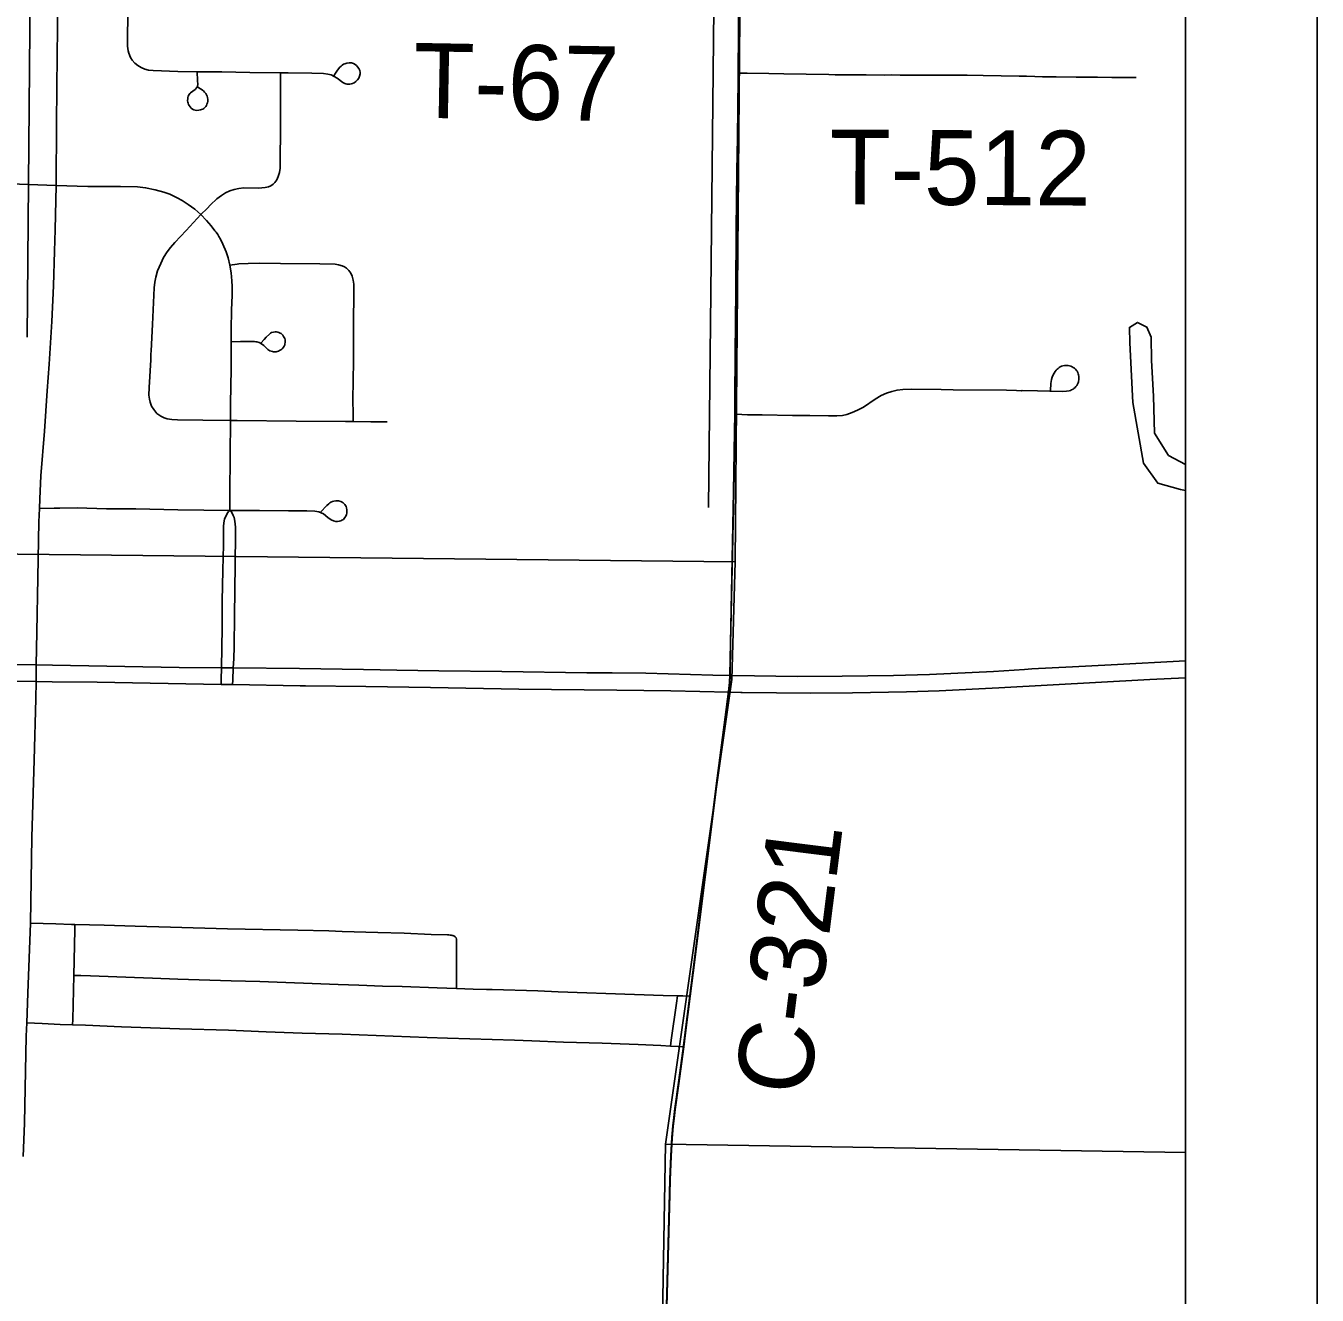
# Model space of a CAD drawing. Extents: x 0 to 34, y 0 to 22.
# Drawn here: x 8.019 to 9, y 17.308 to 18.272 of the extents above; entities that cross this region are included whole.
import ezdxf

# ---------------------------------------------------------------- set-up
doc = ezdxf.new("R2010")
doc.units = 0
for name, color, linetype in [('GM_X_Corporation', 7, 'Continuous'), ('GM_X_County_Road', 7, 'Continuous'), ('GM_X_County_Road_Text', 7, 'Continuous'), ('GM_X_Minor_Lake', 7, 'Continuous'), ('GM_X_Minor_River', 7, 'Continuous'), ('GM_X_State_Route', 7, 'Continuous'), ('GM_X_Township_Road', 7, 'Continuous'), ('GM_X_Township_Road_Text', 7, 'Continuous'), ('SH_Data', 7, 'Continuous')]:
    doc.layers.add(name, color=color, linetype=linetype)

msp = doc.modelspace()

# ---------------------------------------------------------------- linework, layer by layer
at = {"layer": 'GM_X_Corporation'}
for points in [[(2.1, 14.1), (8.9, 14.1), (8.9, 20.9), (5.89055, 20.9)], [(8.9, 14.37894), (8.9, 20.9)], [(8.56052, 18.29711), (8.56015, 18.23686), (8.56012, 18.23234), (8.55954, 18.18707), (8.55908, 18.16202), (8.55853, 18.11743), (8.55826, 18.07146), (8.55781, 18.02296), (8.55745, 17.98877), (8.55741, 17.97779), (8.55735, 17.96394), (8.55646, 17.91855), (8.55413, 17.8032), (8.55384, 17.77938), (8.55343, 17.77344), (8.55279, 17.76663), (8.55006, 17.74716), (8.54421, 17.70088), (8.52569, 17.55343), (8.52344, 17.53573), (8.51965, 17.50581), (8.51853, 17.49739), (8.51481, 17.46953), (8.51202, 17.44979), (8.5112, 17.44296), (8.51046, 17.43679), (8.50973, 17.42799), (8.50887, 17.41389), (8.50817, 17.39625), (8.50787, 17.38524), (8.50714, 17.35667), (8.50556, 17.3001)], [(8.50556, 17.3001), (8.50714, 17.35667), (8.50787, 17.38524), (8.50817, 17.39625), (8.50887, 17.41389), (8.50973, 17.42799), (8.51046, 17.43679), (8.5112, 17.44296), (8.51202, 17.44979), (8.51481, 17.46953), (8.51853, 17.49739), (8.51965, 17.50581), (8.52344, 17.53573), (8.52569, 17.55343), (8.54421, 17.70088), (8.55006, 17.74716), (8.55279, 17.76663), (8.55343, 17.77344), (8.55384, 17.77938), (8.55413, 17.8032), (8.55646, 17.91855), (8.55735, 17.96394), (8.55741, 17.97779), (8.55745, 17.98877), (8.55781, 18.02296), (8.55826, 18.07146), (8.55853, 18.11743), (8.55908, 18.16202), (8.55954, 18.18707), (8.56012, 18.23234), (8.56015, 18.23686), (8.56052, 18.29711)]]:
    msp.add_lwpolyline(points, dxfattribs=at)
for points in [[(7.52848, 18.83427), (8.56457, 18.82324), (8.56257, 18.42645), (8.55788, 17.86518), (7.51498, 17.8763)], [(8.9, 17.41639), (8.9, 18.42344), (8.56257, 18.42645), (8.55788, 17.86518), (8.55531, 17.77577), (8.50493, 17.42275)], [(7.51498, 17.8763), (8.55788, 17.86518), (8.55531, 17.77577), (8.50493, 17.42275), (8.49555, 16.88277), (7.49907, 16.90775)], [(8.9, 16.4075), (8.9, 17.41639), (8.50493, 17.42275), (8.49555, 16.88277), (8.48586, 16.41255)]]:
    msp.add_lwpolyline(points, close=True, dxfattribs=at)
at = {"layer": 'GM_X_County_Road'}
msp.add_line((8.56037, 18.2363), (8.56075, 18.29655), dxfattribs=at)
for points in [[(8.0419, 18.15097), (8.04211, 18.19851), (8.04274, 18.25005), (8.04302, 18.28863), (8.04319, 18.30453)], [(8.55763, 17.97724), (8.55768, 17.98822), (8.55804, 18.02241), (8.55849, 18.0709), (8.55876, 18.11688), (8.55931, 18.16146), (8.55977, 18.18651), (8.56034, 18.23178), (8.56037, 18.2363)], [(8.02909, 17.90551), (8.02935, 17.91304), (8.03033, 17.93044), (8.03291, 17.96425), (8.03512, 17.99497), (8.03647, 18.0152), (8.03868, 18.04766), (8.03983, 18.07469), (8.04065, 18.1011), (8.04115, 18.11736), (8.0419, 18.15097)], [(8.55406, 17.77883), (8.55435, 17.80265), (8.55668, 17.918), (8.55758, 17.96339), (8.55763, 17.97724)], [(8.02662, 17.77409), (8.02676, 17.7849), (8.02679, 17.78677), (8.02712, 17.81165), (8.0279, 17.85327), (8.02874, 17.89539), (8.02909, 17.90551)], [(8.02226, 17.59065), (8.02329, 17.6559), (8.02511, 17.71438), (8.02646, 17.76103), (8.02662, 17.77409)], [(8.55302, 17.76608), (8.55365, 17.77288), (8.55406, 17.77883)], [(8.52367, 17.53518), (8.52591, 17.55287), (8.54444, 17.70032), (8.55029, 17.7466), (8.55302, 17.76608)], [(8.01949, 17.51487), (8.02025, 17.53756), (8.02226, 17.59065)], [(8.51876, 17.49683), (8.51988, 17.50525), (8.52367, 17.53518)], [(8.01675, 17.41339), (8.0177, 17.43885), (8.01916, 17.50487), (8.01949, 17.51487)], [(8.49865, 17.00885), (8.49937, 17.03847), (8.50075, 17.0913), (8.50197, 17.14476), (8.5044, 17.23552), (8.50579, 17.29955), (8.50737, 17.35612), (8.50809, 17.38469), (8.5084, 17.39569), (8.50909, 17.41334), (8.50996, 17.42743), (8.51069, 17.43624), (8.51143, 17.44241), (8.51225, 17.44924), (8.51504, 17.46898), (8.51876, 17.49683)]]:
    msp.add_lwpolyline(points, dxfattribs=at)
at = {"layer": 'GM_X_Minor_Lake'}
msp.add_lwpolyline([(8.9, 17.93891), (8.88708, 17.94598), (8.87634, 17.96282), (8.87557, 17.99092), (8.87403, 18.01789), (8.87388, 18.03573), (8.87058, 18.04337), (8.86344, 18.04688), (8.85735, 18.04316), (8.85758, 18.03138), (8.86002, 17.98618), (8.86812, 17.94014), (8.87887, 17.92482), (8.89619, 17.92005), (8.9, 17.91938)], dxfattribs=at)
at = {"layer": 'GM_X_Minor_River'}
for points in [[(8.55117, 19.1356), (8.54966, 19.01986), (8.54597, 18.88176), (8.54328, 18.70341), (8.54041, 18.48254), (8.54164, 18.28513), (8.53923, 18.06955), (8.53751, 17.90633)], [(8.03098, 18.72881), (8.02449, 18.51975), (8.022, 18.29848), (8.01975, 18.03583)]]:
    msp.add_lwpolyline(points, dxfattribs=at)
at = {"layer": 'GM_X_State_Route'}
msp.add_line((8.55302, 17.76608), (8.56202, 17.76588), dxfattribs=at)
for points in [[(8.55406, 17.77883), (8.57247, 17.77844), (8.60482, 17.77811), (8.63902, 17.77819), (8.6782, 17.77888), (8.70556, 17.77963), (8.72172, 17.78021), (8.75403, 17.7817), (8.77762, 17.78333), (8.78319, 17.78384), (8.81421, 17.7853), (8.8434, 17.78689), (8.9, 17.7898)], [(7.99618, 17.78735), (8.02679, 17.78677), (8.03907, 17.78653), (8.13543, 17.78485), (8.16741, 17.7846), (8.17646, 17.78451), (8.22683, 17.78404), (8.27532, 17.78327), (8.3008, 17.78277), (8.33251, 17.78222), (8.3804, 17.78185), (8.44505, 17.78084), (8.46433, 17.78079), (8.4898, 17.78044), (8.54076, 17.77911), (8.55406, 17.77883)], [(7.95935, 17.77485), (8.02662, 17.77409), (8.03893, 17.77394), (8.07313, 17.77358), (8.16712, 17.77203), (8.17012, 17.77198), (8.17595, 17.77188), (8.2273, 17.77094), (8.23128, 17.77091)], [(8.23128, 17.77091), (8.27705, 17.77052), (8.32617, 17.76968), (8.3933, 17.76838), (8.4679, 17.76756), (8.50894, 17.76706), (8.55302, 17.76608)], [(8.56202, 17.76588), (8.56302, 17.76585), (8.61524, 17.76541), (8.64693, 17.76567), (8.68795, 17.7663), (8.71279, 17.76714), (8.75812, 17.76927), (8.87297, 17.77567), (8.9, 17.77706)]]:
    msp.add_lwpolyline(points, dxfattribs=at)
at = {"layer": 'GM_X_Township_Road'}
for points in [[(8.09655, 18.30419), (8.09648, 18.29765), (8.0961, 18.26281), (8.09616, 18.25666), (8.0966, 18.25311), (8.09704, 18.25143), (8.09841, 18.24811), (8.09964, 18.24612), (8.10157, 18.2439), (8.10385, 18.24199), (8.10638, 18.24045), (8.10912, 18.23931), (8.11201, 18.23857), (8.1156, 18.23815), (8.13421, 18.23745), (8.14909, 18.23736)], [(8.21241, 18.23654), (8.21817, 18.23647), (8.23623, 18.23627), (8.24498, 18.23603), (8.24817, 18.23561), (8.2507, 18.23491), (8.25309, 18.23383), (8.25531, 18.23246), (8.25973, 18.22909), (8.26122, 18.22829), (8.26208, 18.22803), (8.2629, 18.22786), (8.26373, 18.22778), (8.26492, 18.22782), (8.26611, 18.22803), (8.26701, 18.22828), (8.26826, 18.22896), (8.26962, 18.22988), (8.27082, 18.23107), (8.27178, 18.23247), (8.27246, 18.23401), (8.27285, 18.23563), (8.27287, 18.23667), (8.2725, 18.23826), (8.27179, 18.2398), (8.27081, 18.24117), (8.2701, 18.24197), (8.26915, 18.24271), (8.26772, 18.24357), (8.26616, 18.24405), (8.26449, 18.24417), (8.26282, 18.24396), (8.2612, 18.24345), (8.2603, 18.24304), (8.25921, 18.24233), (8.25829, 18.24168), (8.25735, 18.2408), (8.2563, 18.23966), (8.25503, 18.23788), (8.25406, 18.2362), (8.25296, 18.23426)], [(8.14916, 18.22576), (8.15115, 18.22461), (8.15209, 18.22406), (8.15299, 18.22345), (8.15378, 18.22279), (8.15468, 18.22193), (8.15558, 18.22078), (8.15616, 18.21975), (8.15653, 18.21876), (8.15686, 18.2177), (8.15708, 18.21629), (8.15703, 18.2149), (8.15682, 18.21362), (8.15645, 18.21263), (8.15604, 18.21181), (8.15547, 18.21095), (8.15468, 18.20996), (8.15415, 18.20951), (8.15321, 18.20889), (8.15242, 18.20856), (8.15141, 18.20829), (8.1502, 18.20803), (8.14868, 18.20794), (8.14736, 18.20815), (8.14652, 18.20844), (8.14541, 18.20897), (8.14447, 18.20976), (8.14366, 18.21066), (8.14291, 18.21169), (8.14247, 18.21242), (8.14207, 18.21334), (8.14185, 18.21432), (8.14174, 18.21517), (8.14181, 18.21702), (8.14198, 18.21789), (8.14225, 18.21883), (8.1428, 18.21993), (8.14337, 18.22069), (8.14401, 18.22132), (8.14749, 18.22395), (8.14871, 18.22532), (8.14923, 18.22643), (8.14945, 18.22764), (8.14934, 18.23074), (8.14909, 18.23736)], [(8.14909, 18.23736), (8.15223, 18.23735), (8.16779, 18.23718), (8.18894, 18.23678), (8.21241, 18.23654)], [(8.15178, 18.1288), (8.15653, 18.13357), (8.15913, 18.1362), (8.16407, 18.14081), (8.16744, 18.14339), (8.17054, 18.14528), (8.17381, 18.1468), (8.17724, 18.14794), (8.18078, 18.14868), (8.18438, 18.14904), (8.19554, 18.14897), (8.20058, 18.14937), (8.20317, 18.14991), (8.20504, 18.15068), (8.20678, 18.15182), (8.20813, 18.1532), (8.20956, 18.15527), (8.21067, 18.15767), (8.21155, 18.1608), (8.21195, 18.164), (8.21202, 18.17026), (8.21226, 18.19322), (8.21239, 18.22982), (8.21241, 18.23654)], [(8.56037, 18.2363), (8.56682, 18.23621), (8.58345, 18.23599), (8.59476, 18.23584), (8.61174, 18.23548), (8.62894, 18.23512), (8.63388, 18.23506), (8.64087, 18.235), (8.65731, 18.23486), (8.67094, 18.23483), (8.67641, 18.23489), (8.6832, 18.23476), (8.69249, 18.23463), (8.69877, 18.23463), (8.70898, 18.23463), (8.71835, 18.23464), (8.73407, 18.23464), (8.7461, 18.23447), (8.77355, 18.23399), (8.77918, 18.23396), (8.78552, 18.23376), (8.79119, 18.23356), (8.80177, 18.23342), (8.8169, 18.23328), (8.83302, 18.23313), (8.844, 18.23303), (8.8577, 18.23294), (8.86248, 18.23291)], [(7.99503, 18.15257), (8.00701, 18.15228), (8.0419, 18.15097)], [(8.15178, 18.1288), (8.14712, 18.1329), (8.1422, 18.1366), (8.13757, 18.13961), (8.1338, 18.14168), (8.12823, 18.14426), (8.12363, 18.14595), (8.1171, 18.14774), (8.10986, 18.14917), (8.10377, 18.14985), (8.09081, 18.15022), (8.0659, 18.15008), (8.0419, 18.15097)], [(8.11839, 17.97785), (8.11612, 17.98069), (8.11442, 17.98341), (8.11324, 17.98629), (8.11266, 17.98871), (8.11236, 17.9918), (8.11244, 17.99741), (8.11372, 18.01854), (8.11368, 18.01978), (8.11389, 18.02165), (8.11387, 18.02289), (8.11408, 18.02538), (8.11503, 18.04528), (8.11628, 18.07327), (8.11674, 18.0776), (8.11748, 18.08126), (8.11894, 18.08602), (8.12127, 18.09179), (8.12345, 18.09627), (8.1261, 18.10049), (8.12875, 18.10394), (8.13213, 18.1076), (8.14055, 18.11678), (8.15178, 18.1288)], [(8.17386, 18.09047), (8.17254, 18.09599), (8.17099, 18.10063), (8.16859, 18.10629), (8.16665, 18.1102), (8.16553, 18.11231), (8.16464, 18.11378), (8.16346, 18.11549), (8.16252, 18.11647), (8.15957, 18.12017), (8.15603, 18.12445), (8.15178, 18.1288)], [(8.26747, 17.97156), (8.26741, 17.97762), (8.26731, 17.9882), (8.26773, 18.01746), (8.2678, 18.04921), (8.26796, 18.06663), (8.26799, 18.07597), (8.26764, 18.07906), (8.26681, 18.08206), (8.26576, 18.08432), (8.26432, 18.08634), (8.26251, 18.08805), (8.26098, 18.08911), (8.2593, 18.08992), (8.25631, 18.09079), (8.25396, 18.0911), (8.2422, 18.09146), (8.21238, 18.09161), (8.19621, 18.09181), (8.18764, 18.0916), (8.18067, 18.09133), (8.17943, 18.09118), (8.17386, 18.09047)], [(8.17482, 18.0323), (8.17496, 18.04145), (8.17518, 18.0563), (8.17548, 18.06752), (8.17551, 18.0742), (8.17539, 18.0785), (8.17519, 18.08155), (8.17487, 18.08456), (8.17386, 18.09047)], [(8.19347, 18.03228), (8.1944, 18.03215), (8.19618, 18.03161), (8.19787, 18.03069), (8.19953, 18.02939), (8.2028, 18.02638), (8.20351, 18.0259), (8.20429, 18.02544), (8.20528, 18.02503), (8.20616, 18.02481), (8.20705, 18.02467), (8.20803, 18.02463), (8.20902, 18.0247), (8.20988, 18.02487), (8.21071, 18.02508), (8.21164, 18.02551), (8.21252, 18.02602), (8.21323, 18.02651), (8.21414, 18.02736), (8.2147, 18.02812), (8.21512, 18.02894), (8.21552, 18.02993), (8.21573, 18.03072), (8.21585, 18.03166), (8.21593, 18.03258), (8.21575, 18.03381), (8.21551, 18.03467), (8.21511, 18.03557), (8.21469, 18.03635), (8.2141, 18.03714), (8.21358, 18.0377), (8.21272, 18.03842), (8.2121, 18.03882), (8.21108, 18.03931), (8.21033, 18.03956), (8.20926, 18.03974), (8.20828, 18.0398), (8.20708, 18.03964), (8.2056, 18.03916), (8.20474, 18.03873), (8.20384, 18.03807), (8.20145, 18.0358), (8.19979, 18.03389), (8.19746, 18.0312)], [(8.17431, 17.97255), (8.17445, 17.98535), (8.17474, 18.01139), (8.1748, 18.019), (8.17481, 18.02068), (8.1748, 18.02301), (8.1748, 18.02663), (8.17482, 18.0323)], [(8.17482, 18.0323), (8.18192, 18.03234), (8.19255, 18.0324), (8.19347, 18.03228)], [(8.55763, 17.97724), (8.56275, 17.97698), (8.56713, 17.97675), (8.57834, 17.97669), (8.60135, 17.97626), (8.61442, 17.97619), (8.62872, 17.97594), (8.63504, 17.97607), (8.63946, 17.97634), (8.64258, 17.97705), (8.64675, 17.97846), (8.6508, 17.98025), (8.65525, 17.98269), (8.66408, 17.98853), (8.66884, 17.99131), (8.67271, 17.9931), (8.67673, 17.99451), (8.68087, 17.99549), (8.68508, 17.99605), (8.69184, 17.99626), (8.71418, 17.99605), (8.72353, 17.99582), (8.76397, 17.99546), (8.77144, 17.99512), (8.77517, 17.99503), (8.77577, 17.9952), (8.78757, 17.99498), (8.80636, 17.99443), (8.80943, 17.99473), (8.81156, 17.995), (8.81263, 17.99534), (8.81346, 17.99574), (8.81452, 17.99633), (8.81519, 17.99684), (8.81604, 17.99756), (8.81668, 17.99824), (8.81735, 17.99909), (8.8179, 17.99992), (8.81839, 18.00094), (8.81868, 18.00184), (8.81901, 18.00388), (8.81891, 18.00593), (8.81867, 18.00706), (8.81846, 18.00794), (8.81805, 18.00896), (8.81756, 18.0098), (8.81706, 18.01052), (8.81626, 18.01143), (8.81554, 18.01208), (8.81464, 18.01271), (8.81389, 18.01315), (8.81279, 18.01363), (8.81184, 18.01393), (8.81081, 18.01416), (8.8099, 18.0143), (8.80874, 18.01428), (8.80793, 18.01418), (8.8067, 18.01393), (8.80583, 18.01364), (8.80479, 18.01315), (8.80403, 18.01269), (8.80311, 18.01199), (8.80246, 18.01142), (8.80167, 18.01057), (8.80094, 18.00969), (8.8001, 18.00846), (8.79938, 18.00718), (8.79856, 18.00526), (8.79807, 18.00352), (8.79769, 18.00043), (8.79734, 17.99518)], [(8.11839, 17.97785), (8.1214, 17.97578), (8.12404, 17.97446), (8.12628, 17.97375), (8.1298, 17.97313), (8.13409, 17.97288), (8.15333, 17.97259), (8.17431, 17.97255)], [(8.17378, 17.90418), (8.17385, 17.91628), (8.174, 17.94613), (8.17431, 17.97255)], [(8.17431, 17.97255), (8.17952, 17.97255), (8.22434, 17.97194), (8.26169, 17.97163), (8.26747, 17.97156)], [(8.26747, 17.97156), (8.28098, 17.97138), (8.29343, 17.97134)], [(8.21828, 17.90389), (8.23225, 17.90381), (8.23841, 17.90346), (8.24148, 17.90299), (8.24324, 17.90239), (8.24488, 17.90152), (8.2483, 17.89884), (8.25084, 17.89704), (8.25252, 17.89622), (8.25433, 17.8958), (8.25567, 17.89568), (8.25695, 17.89586), (8.25805, 17.89615), (8.25904, 17.89662), (8.26009, 17.89732), (8.26131, 17.89865), (8.26201, 17.89988), (8.26242, 17.90104), (8.26265, 17.90215), (8.26274, 17.90341), (8.26282, 17.90459), (8.26253, 17.9061), (8.26214, 17.90705), (8.26171, 17.90784), (8.26119, 17.90865), (8.26073, 17.90918), (8.25986, 17.90994), (8.25915, 17.9104), (8.25823, 17.91084), (8.25643, 17.91134), (8.25457, 17.91143), (8.25275, 17.91109), (8.25171, 17.9108), (8.25056, 17.91033), (8.24973, 17.90981), (8.24895, 17.90922), (8.2474, 17.90788), (8.24282, 17.90277)], [(8.02909, 17.90551), (8.04041, 17.90575), (8.04476, 17.90584), (8.0578, 17.90599), (8.08016, 17.90543), (8.10252, 17.90523), (8.1342, 17.90471), (8.17378, 17.90418)], [(8.16712, 17.77203), (8.1672, 17.77572), (8.16741, 17.7846), (8.16812, 17.81527), (8.16807, 17.83519), (8.1686, 17.85885), (8.16903, 17.8781), (8.16892, 17.89204), (8.1693, 17.89466), (8.16985, 17.89742), (8.17079, 17.89989), (8.17219, 17.90257), (8.17288, 17.90341), (8.17378, 17.90418)], [(8.17818, 17.89042), (8.17816, 17.89148), (8.17769, 17.89588), (8.177, 17.89868), (8.1764, 17.90038), (8.17545, 17.90246), (8.17481, 17.90326), (8.17378, 17.90418)], [(8.17378, 17.90418), (8.18141, 17.90407), (8.19633, 17.90402), (8.21828, 17.90389)], [(8.17646, 17.78451), (8.17674, 17.79152), (8.17711, 17.80073), (8.17734, 17.824), (8.17778, 17.86315), (8.17823, 17.88617), (8.17818, 17.89042)], [(8.17595, 17.77188), (8.17609, 17.77523), (8.17646, 17.78451)], [(8.02226, 17.59065), (8.0417, 17.59009), (8.05347, 17.58963), (8.05605, 17.58958)], [(8.05518, 17.55085), (8.05596, 17.58553), (8.05605, 17.58958)], [(8.05605, 17.58958), (8.07833, 17.5891), (8.10192, 17.58834), (8.12863, 17.58764), (8.17211, 17.58638), (8.22554, 17.58539), (8.24915, 17.58472), (8.25907, 17.58426), (8.28638, 17.58349), (8.30627, 17.58307), (8.32676, 17.58209), (8.33918, 17.58173), (8.34012, 17.58169), (8.34111, 17.58164), (8.34193, 17.58154), (8.3427, 17.58141), (8.34336, 17.5813), (8.34397, 17.58111), (8.34503, 17.58039)], [(8.34593, 17.54104), (8.34595, 17.5446), (8.34608, 17.57579), (8.34609, 17.57742), (8.34597, 17.57851), (8.3457, 17.57947), (8.34503, 17.58039)], [(8.05433, 17.5134), (8.05442, 17.51752), (8.05518, 17.55085)], [(8.05518, 17.55085), (8.06051, 17.55081), (8.06794, 17.55076), (8.10148, 17.54928), (8.11516, 17.5488), (8.13443, 17.54816), (8.17484, 17.54698), (8.19659, 17.54637), (8.25625, 17.54403), (8.27179, 17.54348), (8.28982, 17.54291), (8.30474, 17.54249), (8.33146, 17.54155), (8.34593, 17.54104)], [(8.34593, 17.54104), (8.35881, 17.54058), (8.36875, 17.54028), (8.3731, 17.5402), (8.40789, 17.53915), (8.42342, 17.53848), (8.48123, 17.53646), (8.503, 17.53583), (8.51385, 17.53549)], [(8.50863, 17.49729), (8.50924, 17.50175), (8.5131, 17.52999), (8.51385, 17.53549)], [(8.51385, 17.53549), (8.5179, 17.53536), (8.52367, 17.53518)], [(8.01949, 17.51487), (8.0313, 17.51434), (8.04494, 17.51373), (8.05433, 17.5134)], [(8.05433, 17.5134), (8.06419, 17.51307), (8.09151, 17.51196), (8.13559, 17.51038), (8.17287, 17.50928), (8.20143, 17.50822), (8.22874, 17.50714), (8.25918, 17.50626), (8.32377, 17.50393), (8.33929, 17.50332), (8.39021, 17.50177), (8.40326, 17.5013), (8.42747, 17.50035), (8.45666, 17.49947), (8.47033, 17.49896), (8.48398, 17.49842), (8.5013, 17.49763), (8.50863, 17.49729)], [(8.50863, 17.49729), (8.51446, 17.49703), (8.51876, 17.49683)]]:
    msp.add_lwpolyline(points, dxfattribs=at)
at = {"layer": 'SH_Data'}
for p, q in [((9, 21), (9, 14)), ((9, 21), (9, 14)), ((8.9, 20.9), (8.9, 14.1)), ((8.9, 20.9), (8.9, 14.1))]:
    msp.add_line(p, q, dxfattribs=at)

# ---------------------------------------------------------------- texts
at = {"layer": 'GM_X_County_Road_Text'}
msp.add_text('C-321', height=0.056818, rotation=82.84236, dxfattribs=at).set_placement((8.61381, 17.45829))
at = {"layer": 'GM_X_Township_Road_Text'}
for s, rotation, p in [('T-67', 358.97025, (8.3128, 18.20247)), ('T-512', 359.72573, (8.62943, 18.13662))]:
    msp.add_text(s, height=0.056818, rotation=rotation, dxfattribs=at).set_placement(p)

doc.saveas('drawing.dxf')
